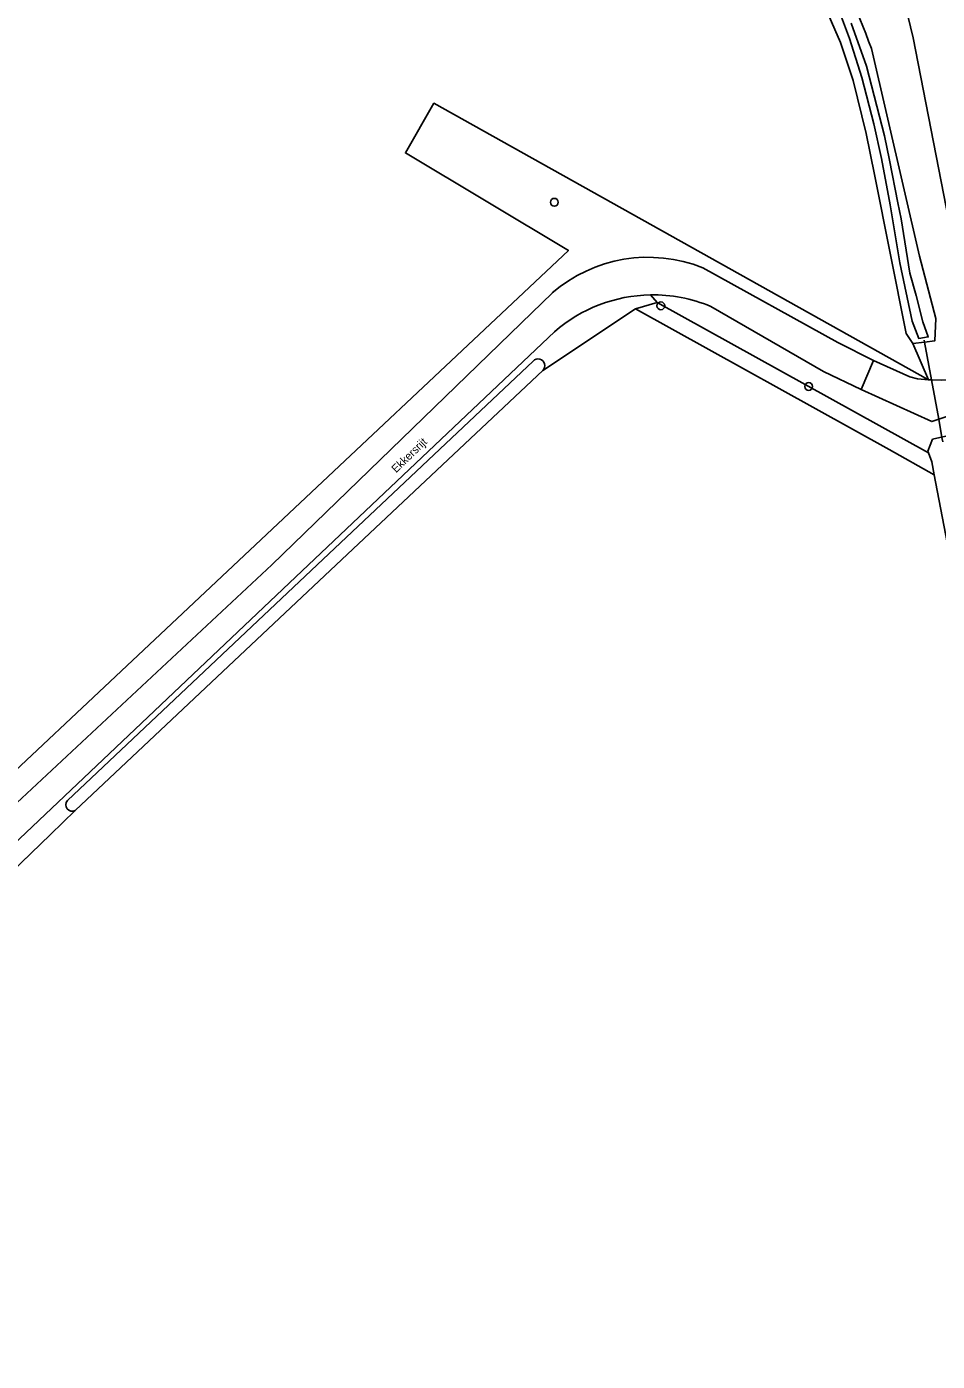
# Model space of a CAD drawing. Extents: x 155209 to 156748, y 385356 to 388487.
# Drawn here: x 155870 to 155983.7, y 387150.5 to 387317.3 of the extents above; entities that cross this region are included whole.
import ezdxf

# ---------------------------------------------------------------- set-up
doc = ezdxf.new("R2010")
doc.units = 0
for name, color, linetype in [('IMGEO_Berm_groen', 7, 'Continuous'), ('IMGEO_Boom', 7, 'Continuous'), ('IMGEO_Bouwland', 7, 'Continuous'), ('IMGEO_Duiker', 7, 'Continuous'), ('IMGEO_Groenvoorziening', 7, 'Continuous'), ('IMGEO_Oever', 7, 'Continuous'), ('IMGEO_Openbare_ruimte_label', 7, 'Continuous'), ('IMGEO_Rijbaan_lokaal_gesloten', 7, 'Continuous'), ('IMGEO_Rijbaan_lokaal_halfverhard', 7, 'Continuous'), ('IMGEO_Rijbaan_lokaal_onverhard', 7, 'Continuous'), ('IMGEO_Waterloop', 7, 'Continuous')]:
    doc.layers.add(name, color=color, linetype=linetype)

msp = doc.modelspace()

# ---------------------------------------------------------------- linework, layer by layer
at = {"layer": 'IMGEO_Berm_groen'}
for points in [[(155934.44, 387274.3), (155946.02, 387282), (155948.71, 387282.8), (155947.88, 387283.75)], [(155947.88, 387283.75), (155948.71, 387282.8), (155982.58, 387264.03), (155982.51, 387264.23), (155983.11, 387265.71), (155985.52, 387266.24), (155987.41, 387263.41), (156023.19, 387074.38), (156023.15, 387072.76), (156022.07, 387071.71), (156020.54, 387071.32), (156012.96, 387067.09), (156012.12, 387066.35), (156011.18, 387065.51), (156010.73, 387065.11), (156010.1, 387065.36), (156008.59, 387064.11), (156010.29, 387063.34)], [(155969.49, 387274.19), (155955.4, 387282.31)], [(155935.88, 387279.15), (155905.19, 387250), (155811.33, 387161.02), (155799.75, 387150.14), (155800.58, 387149.78), (155802.15, 387149.1), (155805.58, 387152.26), (155808.2, 387155.21)], [(155875.08, 387220.55), (155906.25, 387250), (155933.23, 387275.48)], [(156025.74, 387080.22), (156009.76, 387164.56), (155992.17, 387256.24), (155990.17, 387266.67), (155989.94, 387268.35), (155987.99, 387269.6), (155983.87, 387268.2), (155983.02, 387267.92), (155974.17, 387271.92), (155969.49, 387274.19)], [(155866.82, 387210.39), (155872.95, 387216.32), (155876.05, 387219.32)]]:
    msp.add_lwpolyline(points, dxfattribs=at)
for centre, radius, start, end in [((155948.19, 387264.98), 18.77, 90.9503, 130.9761), ((155948.18, 387264.96), 18.79, 67.4114, 90.9339), ((155933.84, 387274.9), 0.848, 315.1473, 136.4773), ((155875.68, 387220.03), 0.798, 139.3523, 297.3731)]:
    msp.add_arc(centre, radius, start, end, dxfattribs=at)
at = {"layer": 'IMGEO_Boom'}
for centre in [(155935.88, 387295.32), (155949.18, 387282.38), (155967.63, 387272.3)]:
    msp.add_circle(centre, 0.489, dxfattribs=at)
at = {"layer": 'IMGEO_Bouwland'}
msp.add_lwpolyline([(155589.37, 387232.7), (155593.22, 387231.16), (155614.4, 387224.24), (155650.88, 387209.57), (155681.28, 387197.24), (155744.89, 387171.18), (155773.46, 387244.47), (155781.14, 387242.22), (155852.44, 387209.14), (155937.64, 387289.31), (155917.27, 387301.48), (155920.84, 387307.7), (155982.59, 387273.13), (155980.66, 387277.68), (155979.82, 387278.93), (155975.84, 387298.77), (155974.83, 387303.91), (155973.18, 387310.52), (155971.62, 387315.3), (155969.78, 387319.47), (155968.04, 387323.12), (155966.34, 387326.38), (155962.23, 387332.69), (155958.47, 387337.93)], dxfattribs=at)
msp.add_lwpolyline([(155983.31, 387261.26), (155977.7, 387264.44), (155946.02, 387282), (155934.44, 387274.3), (155908.63, 387250), (155876.05, 387219.32), (155872.95, 387216.32), (155866.82, 387210.39), (155866.68, 387210.25), (155829.99, 387175.53), (155824.39, 387170.24), (155820.32, 387166.38), (155820.46, 387166.24), (155817.28, 387163.02), (155817.14, 387163.16), (155808.2, 387155.21), (155805.58, 387152.26), (155802.15, 387149.1), (155805.27, 387147.74), (155854.95, 387128.34), (156000, 387072.11), (156012.96, 387067.09), (156020.54, 387071.32), (156019.65, 387072.07)], close=True, dxfattribs=at)
at = {"layer": 'IMGEO_Duiker'}
msp.add_lwpolyline([(155982.06, 387278.09), (155982.1, 387277.85), (155982.97, 387273.12), (155983.87, 387268.2), (155984.28, 387265.92), (155984.39, 387265.37)], dxfattribs=at)
at = {"layer": 'IMGEO_Groenvoorziening'}
for points in [[(155975.47, 387314.53), (155981.46, 387288.59), (155983.5, 387280.81), (155983.39, 387278.01), (155982.1, 387277.85), (155980.66, 387277.68), (155982.59, 387273.13), (155982.72, 387273.12), (155982.97, 387273.12), (155984.18, 387273.11), (155987.28, 387273.29), (155988.51, 387275.75), (155987.67, 387279.96), (155980.67, 387315.87)], [(155920.84, 387307.7), (155917.27, 387301.48), (155937.64, 387289.31), (155852.44, 387209.14), (155846.1, 387202.2)], [(155954.4, 387287.12), (155971.27, 387277.81), (155975.71, 387275.56), (155980.25, 387273.52), (155981.23, 387273.25), (155982.59, 387273.13), (155920.84, 387307.7)], [(155830.95, 387186.71), (155832.39, 387187.53), (155834.38, 387189.06), (155861.21, 387213.3), (155900.6, 387250), (155933.07, 387281.51), (155935.61, 387283.98)]]:
    msp.add_lwpolyline(points, dxfattribs=at)
msp.add_lwpolyline([(155948.71, 387282.8), (155946.02, 387282), (155977.7, 387264.44), (155983.31, 387261.26), (155983, 387262.89), (155982.58, 387264.03)], close=True, dxfattribs=at)
for centre, radius, start, end in [((155845.57, 387285.48), 138.48, 12.6792, 49.4239), ((155897.75, 387286.71), 82.54, 19.6901, 30.7711), ((155947.58, 387270.17), 18.28, 68.0909, 130.8991)]:
    msp.add_arc(centre, radius, start, end, dxfattribs=at)
at = {"layer": 'IMGEO_Oever'}
for points in [[(155969.78, 387319.47), (155971.62, 387315.3), (155973.18, 387310.52), (155974.83, 387303.91), (155975.84, 387298.77), (155979.82, 387278.93), (155980.66, 387277.68), (155982.1, 387277.85), (155983.39, 387278.01), (155983.5, 387280.81), (155981.46, 387288.59), (155975.47, 387314.53)], [(155972.93, 387317.71), (155974.85, 387312.34), (155977.1, 387303.64), (155977.72, 387300.56), (155978.78, 387295.26), (155979.17, 387293.26), (155980.27, 387286.47), (155981.05, 387283.65), (155981.9, 387280.36), (155982.56, 387278.5), (155981.38, 387278.31), (155980.56, 387280.48), (155979.01, 387287.77), (155977.81, 387295.02), (155976.71, 387300.8), (155975.79, 387305.12), (155974.28, 387310.9), (155972.72, 387315.77), (155971.48, 387319.12)]]:
    msp.add_lwpolyline(points, dxfattribs=at)
msp.add_lwpolyline([(155982.58, 387264.03), (155983, 387262.89), (155983.31, 387261.26), (156019.65, 387072.07), (156020.54, 387071.32), (156022.07, 387071.71), (156023.15, 387072.76), (156023.19, 387074.38), (155987.41, 387263.41), (155985.52, 387266.24), (155983.11, 387265.71), (155982.51, 387264.23)], close=True, dxfattribs=at)
msp.add_arc((155897.75, 387286.71), 82.54, 19.6901, 30.7711, dxfattribs=at)
at = {"layer": 'IMGEO_Rijbaan_lokaal_gesloten'}
msp.add_lwpolyline([(155980.67, 387315.87), (155987.67, 387279.96), (155988.51, 387275.75), (155989.94, 387268.35), (155990.17, 387266.67), (155992.17, 387256.24), (156009.76, 387164.56), (156025.74, 387080.22)], dxfattribs=at)
msp.add_arc((155845.57, 387285.48), 138.48, 12.6792, 49.4239, dxfattribs=at)
at = {"layer": 'IMGEO_Rijbaan_lokaal_halfverhard'}
msp.add_lwpolyline([(155987.28, 387273.29), (155984.18, 387273.11), (155982.97, 387273.12), (155982.72, 387273.12), (155982.59, 387273.13), (155981.23, 387273.25), (155980.25, 387273.52), (155975.71, 387275.56), (155974.17, 387271.92), (155983.02, 387267.92), (155983.87, 387268.2), (155987.99, 387269.6)], close=True, dxfattribs=at)
at = {"layer": 'IMGEO_Rijbaan_lokaal_onverhard'}
for points in [[(155955.4, 387282.31), (155969.49, 387274.19), (155974.17, 387271.92), (155975.71, 387275.56), (155971.27, 387277.81), (155954.4, 387287.12)], [(155935.61, 387283.98), (155933.07, 387281.51), (155900.6, 387250), (155861.21, 387213.3), (155834.38, 387189.06), (155832.39, 387187.53), (155830.95, 387186.71)], [(155821.68, 387176.53), (155792.97, 387148.4), (155783.96, 387139.94), (155756.84, 387113.86), (155698.02, 387058.78), (155700.72, 387056.35), (155701.85, 387057.41), (155730.2, 387083.45), (155741.87, 387094.48), (155760.02, 387111.9), (155774.91, 387126.23), (155788.34, 387139.42), (155799.75, 387150.14), (155811.33, 387161.02), (155905.19, 387250), (155935.88, 387279.15)]]:
    msp.add_lwpolyline(points, dxfattribs=at)
for centre, radius, start, end in [((155947.58, 387270.17), 18.28, 68.0909, 130.8991), ((155948.19, 387264.98), 18.77, 90.9503, 130.9761), ((155948.18, 387264.96), 18.79, 67.4114, 90.9339)]:
    msp.add_arc(centre, radius, start, end, dxfattribs=at)
at = {"layer": 'IMGEO_Waterloop'}
for points in [[(155971.48, 387319.12), (155972.72, 387315.77), (155974.28, 387310.9), (155975.79, 387305.12), (155976.71, 387300.8), (155977.81, 387295.02), (155979.01, 387287.77), (155980.56, 387280.48), (155981.38, 387278.31), (155982.56, 387278.5), (155981.9, 387280.36), (155981.05, 387283.65), (155980.27, 387286.47), (155979.17, 387293.26), (155978.78, 387295.26), (155977.72, 387300.56), (155977.1, 387303.64), (155974.85, 387312.34), (155972.93, 387317.71)], [(155933.23, 387275.48), (155906.25, 387250), (155875.08, 387220.55)], [(155876.05, 387219.32), (155908.63, 387250), (155934.44, 387274.3)]]:
    msp.add_lwpolyline(points, dxfattribs=at)
for centre, radius, start, end in [((155933.84, 387274.9), 0.848, 315.1473, 136.4773), ((155875.68, 387220.03), 0.798, 139.3523, 297.3731)]:
    msp.add_arc(centre, radius, start, end, dxfattribs=at)

# ---------------------------------------------------------------- texts
at = {"layer": 'IMGEO_Openbare_ruimte_label'}
msp.add_text('Ekkersrijt', height=1, rotation=43.9466, dxfattribs=at).set_placement((155916.11, 387261.45))

doc.saveas('drawing.dxf')
